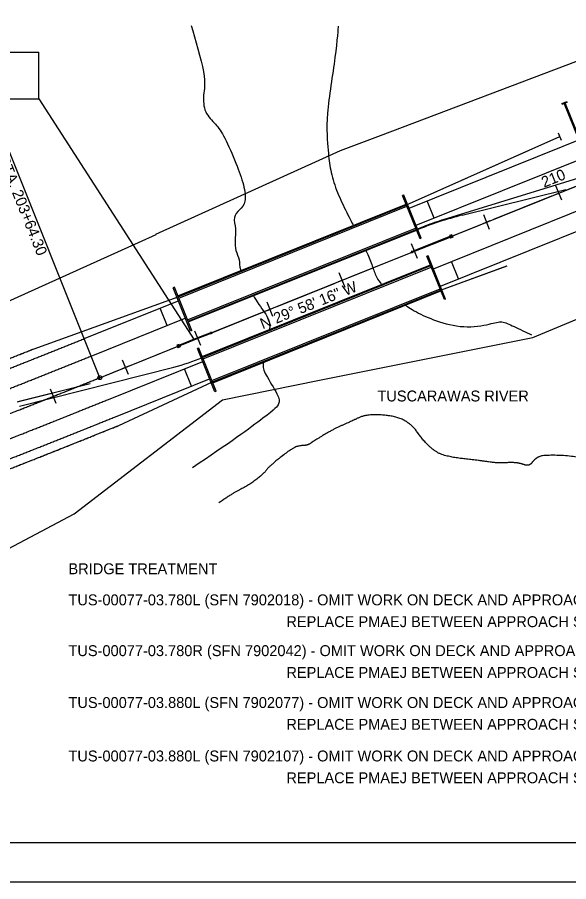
# Model space of a CAD drawing. Extents: x 0 to 3400, y 0 to 2200.
# Drawn here: x 2284 to 2993, y 0 to 1110 of the extents above; entities that cross this region are included whole.
import ezdxf

# ---------------------------------------------------------------- set-up
doc = ezdxf.new("R2010")
doc.units = 0
for name, color, linetype in [('Default', 7, 'Continuous'), ('DR_X_Culvert', 7, 'Continuous'), ('GE_P_CL_100', 7, 'Continuous'), ('HY_X_Text', 7, 'Continuous'), ('HY_X_Water_Edge', 7, 'Continuous'), ('PV_P_EOP', 7, 'Continuous'), ('RD_P_GR_Rt_Replaced', 7, 'Continuous'), ('RD_X_GR_Lt', 7, 'Continuous'), ('RD_X_GR_Rt', 7, 'Continuous'), ('RW_X_Esmt_LA', 7, 'Continuous'), ('SC_Scratch10', 7, 'Continuous'), ('SH_Border', 7, 'Continuous'), ('SH_Cut_Line', 7, 'Continuous'), ('SH_Data', 7, 'Continuous')]:
    doc.layers.add(name, color=color, linetype=linetype)

msp = doc.modelspace()

# ---------------------------------------------------------------- linework, layer by layer
at = {"layer": 'Default'}
for p, q in [((2784.4, 868.8), (2958.6, 946.4)), ((2784.4, 868.8), (2958.6, 946.4)), ((2516.4, 697.6), (3073.1, 921.3)), ((2856.1, 855.7), (2989.4, 888.6)), ((2856.1, 855.7), (2989.4, 888.6)), ((2984.1, 874.7), (2976.6, 893.3)), ((2781.1, 881.5), (2779.5, 880.9)), ((2801.9, 825.2), (2779.5, 880.9)), ((2803.5, 825.9), (2781.1, 881.5)), ((2980.3, 884), (2980.3, 884)), ((2983.1, 885.1), (2983.1, 885.1)), ((2490.8, 751.9), (2784, 869.7)), ((2491.1, 751), (2784.4, 868.8)), ((2491.9, 749.2), (2785.1, 867)), ((2820, 851.9), (2811, 874.2)), ((2891.3, 837.4), (2883.8, 856)), ((2503.1, 721.3), (2796.3, 839.1)), ((2503.8, 719.5), (2797, 837.3)), ((2504.2, 718.5), (2797.4, 836.3)), ((2803.5, 825.9), (2801.9, 825.2)), ((2798.5, 800.1), (2791, 818.7)), ((2812.4, 803.6), (2810.8, 802.9)), ((2833.2, 747.3), (2810.8, 802.9)), ((2834.8, 747.9), (2812.4, 803.6)), ((2522.1, 674), (2815.3, 791.8)), ((2522.5, 673.1), (2815.7, 790.9)), ((2523.2, 671.2), (2816.4, 789)), ((2828.3, 759.3), (2913.9, 790.6)), ((2828.3, 759.3), (2913.6, 790.5)), ((2851.3, 773.9), (2842.4, 796.2)), ((2705.7, 762.9), (2698.2, 781.4)), ((2486.3, 763.1), (2484.7, 762.4)), ((2507, 706.8), (2484.7, 762.4)), ((2508.7, 707.4), (2486.3, 763.1)), ((2534.4, 643.4), (2827.6, 761.2)), ((2535.1, 641.5), (2828.3, 759.3)), ((2535.5, 640.6), (2828.7, 758.4)), ((2306.1, 684.2), (2491.1, 751)), ((2306.1, 684.2), (2491.1, 751)), ((2612.9, 725.6), (2605.4, 744.1)), ((2834.8, 747.9), (2833.2, 747.3)), ((2477.1, 714.1), (2468.2, 736.4)), ((2508.7, 707.4), (2507, 706.8)), ((2520.1, 688.3), (2512.6, 706.8)), ((2390.5, 647), (2516.4, 697.6)), ((2517.6, 685.1), (2516, 684.5)), ((2538.4, 628.8), (2516, 684.5)), ((2540, 629.5), (2517.6, 685.1)), ((2427.3, 651), (2419.8, 669.6)), ((2287.1, 610.4), (2485.6, 660.4)), ((2508.4, 636.2), (2499.5, 658.5)), ((2285.3, 616.4), (2378, 639.4)), ((2378, 639.4), (2378, 639.4)), ((2415.1, 585.7), (2535.1, 641.5)), ((2415.1, 585.7), (2535.1, 641.5)), ((2334.5, 613.8), (2327.1, 632.3)), ((2540, 629.5), (2538.4, 628.8)), ((2287.1, 610.4), (2287.1, 610.4))]:
    msp.add_line(p, q, dxfattribs=at)
for points in [[(2989.6, 887.7), (3063.8, 917.5)], [(2896.8, 850.4), (2971.1, 880.3)], [(2975.7, 882.1), (2985, 885.8)], [(2882.9, 844.8), (2892.2, 848.6)], [(2804, 813.1), (2878.3, 843)], [(2711.2, 775.9), (2785.5, 805.7)], [(2618.4, 738.6), (2692.7, 768.4)], [(2697.3, 770.3), (2706.6, 774)], [(2604.5, 733), (2613.8, 736.7)], [(2525.7, 701.3), (2599.9, 731.1)], [(2432.9, 664), (2507.1, 693.8)], [(2340.1, 626.8), (2341.9, 627.5), (2344.8, 628.6), (2347.7, 629.8), (2350.5, 630.9), (2353.4, 632.1), (2356.2, 633.2), (2359.1, 634.4), (2361.9, 635.5), (2364.8, 636.7), (2367.6, 637.8), (2370.5, 639), (2373.4, 640.1), (2376.2, 641.2), (2379.1, 642.4), (2381.9, 643.5), (2384.8, 644.7), (2387.6, 645.8), (2390.5, 647), (2390.5, 647), (2414.3, 656.6)], [(2418.9, 658.4), (2423.6, 660.3)], [(2423.6, 660.3), (2428.2, 662.1)], [(2326.1, 621.2), (2327.6, 621.8), (2330.5, 622.9), (2330.8, 623)], [(2330.8, 623), (2333.4, 624.1), (2335.4, 624.9)], [(2281.9, 603.7), (2284.7, 604.8), (2287.6, 605.9), (2290.5, 607), (2293.3, 608.2), (2296.2, 609.3), (2299.1, 610.4), (2301.9, 611.6), (2304.8, 612.7), (2307.6, 613.8), (2310.5, 615), (2313.4, 616.1), (2316.2, 617.2), (2319.1, 618.4), (2321.5, 619.3)]]:
    msp.add_lwpolyline(points, dxfattribs=at)
for centre, radius, start, end in [((2956.4, 449.7), 418.1, 103.87, 112.4671), ((2956.4, 449.7), 418.1, 103.87, 112.4671), ((2401.1, 966.1), 317.2, 285.4481, 292.5011)]:
    msp.add_arc(centre, radius, start, end, dxfattribs=at)
for points in [[(2219.8, 650.3), (2223.7, 651.8), (2229.3, 654), (2235, 656.2), (2240.7, 658.4), (2246.4, 660.6), (2252.1, 662.9), (2257.7, 665.1), (2263.4, 667.3), (2269.1, 669.6), (2274.8, 671.8), (2280.5, 674.1), (2286.1, 676.3), (2291.8, 678.6), (2297.5, 680.8), (2303.2, 683.1), (2306.1, 684.2)], [(2219.8, 650.3), (2223.7, 651.8), (2229.3, 654), (2235, 656.2), (2240.7, 658.4), (2246.4, 660.6), (2252.1, 662.9), (2257.7, 665.1), (2263.4, 667.3), (2269.1, 669.6), (2274.8, 671.8), (2280.5, 674.1), (2286.1, 676.3), (2291.8, 678.6), (2297.5, 680.8), (2303.2, 683.1), (2306.1, 684.2)], [(2140.2, 550.2), (2143.7, 551.5), (2149.5, 553.5), (2155.3, 555.6), (2161.1, 557.7), (2166.9, 559.8), (2172.6, 562), (2178.4, 564.1), (2184.2, 566.2), (2190, 568.4), (2195.7, 570.5), (2201.5, 572.7), (2207.2, 574.9), (2213, 577), (2218.8, 579.2), (2224.5, 581.4), (2230.3, 583.6), (2236, 585.8), (2241.7, 588), (2247.5, 590.2), (2253.2, 592.5), (2259, 594.7), (2264.7, 596.9), (2270.4, 599.2), (2276.2, 601.4), (2281.9, 603.7), (2287.6, 605.9), (2293.3, 608.2), (2299.1, 610.4), (2304.8, 612.7), (2310.5, 615), (2316.2, 617.2), (2321.9, 619.5), (2327.6, 621.8), (2333.4, 624.1), (2339.1, 626.4), (2344.8, 628.6), (2350.5, 630.9), (2356.2, 633.2), (2361.9, 635.5), (2367.6, 637.8), (2373.4, 640.1), (2379.1, 642.4), (2384.8, 644.7), (2390.5, 647)], [(2173.9, 492.2), (2177.8, 493.6), (2183.7, 495.7), (2189.5, 497.9), (2195.4, 500), (2201.3, 502.2), (2207.2, 504.3), (2213, 506.5), (2218.9, 508.7), (2224.7, 510.9), (2230.6, 513.1), (2236.4, 515.3), (2242.2, 517.5), (2248.1, 519.7), (2253.9, 522), (2259.7, 524.2), (2265.5, 526.4), (2271.3, 528.7), (2277.1, 530.9), (2282.9, 533.2), (2288.7, 535.4), (2294.5, 537.7), (2300.3, 540), (2306, 542.2), (2311.8, 544.5), (2317.6, 546.8), (2323.3, 549.1), (2329.1, 551.3), (2334.9, 553.6), (2340.6, 555.9), (2346.4, 558.2), (2352.1, 560.5), (2357.8, 562.8), (2363.6, 565.1), (2369.3, 567.4), (2375.1, 569.7), (2380.8, 572), (2386.5, 574.3), (2392.2, 576.6), (2397.9, 578.9), (2403.7, 581.2), (2409.4, 583.4), (2415.1, 585.7)], [(2173.9, 492.2), (2177.8, 493.6), (2183.7, 495.7), (2189.5, 497.9), (2195.4, 500), (2201.3, 502.2), (2207.2, 504.3), (2213, 506.5), (2218.9, 508.7), (2224.7, 510.9), (2230.6, 513.1), (2236.4, 515.3), (2242.2, 517.5), (2248.1, 519.7), (2253.9, 522), (2259.7, 524.2), (2265.5, 526.4), (2271.3, 528.7), (2277.1, 530.9), (2282.9, 533.2), (2288.7, 535.4), (2294.5, 537.7), (2300.3, 540), (2306, 542.2), (2311.8, 544.5), (2317.6, 546.8), (2323.3, 549.1), (2329.1, 551.3), (2334.9, 553.6), (2340.6, 555.9), (2346.4, 558.2), (2352.1, 560.5), (2357.8, 562.8), (2363.6, 565.1), (2369.3, 567.4), (2375.1, 569.7), (2380.8, 572), (2386.5, 574.3), (2392.2, 576.6), (2397.9, 578.9), (2403.7, 581.2), (2409.4, 583.4), (2415.1, 585.7)]]:
    msp.add_spline(points, degree=3, dxfattribs=at)
at = {"layer": 'DR_X_Culvert'}
for p, q in [((2984.2, 999.1), (2990.7, 1001.7)), ((2984.2, 999.1), (2984.6, 998.1)), ((2984.6, 998.1), (2991.1, 1000.7)), ((3025.2, 904.7), (2986.9, 1000.1)), ((3026.4, 905.2), (2988, 1000.6)), ((2990.7, 1001.7), (2991.1, 1000.7)), ((2841, 828.5), (2790.9, 808.4)), ((2841.3, 827.6), (2791.2, 807.5)), ((2843, 830.6), (2839.9, 829.4)), ((2839.9, 829.4), (2841.1, 826.3)), ((2842.6, 829.7), (2840.8, 829)), ((2840.8, 829), (2841.5, 827.1)), ((2841.1, 828.1), (2841.1, 828.1)), ((2844.2, 827.5), (2841.1, 826.3)), ((2843.4, 827.9), (2841.5, 827.1)), ((2842.6, 829.7), (2843.4, 827.9)), ((2843, 830.6), (2844.2, 827.5)), ((2791.6, 809.1), (2790.7, 808.8)), ((2790.7, 808.8), (2791.4, 807.1)), ((2791, 807.9), (2791, 807.9)), ((2792.3, 807.4), (2791.4, 807.1)), ((2791.6, 809.1), (2792.3, 807.4)), ((2533.8, 705.1), (2516.2, 698)), ((2534.2, 704.2), (2516.6, 697.1)), ((2533.7, 705.5), (2532.7, 705.1)), ((2532.7, 705.1), (2533.4, 703.4)), ((2534.4, 703.8), (2533.4, 703.4)), ((2533.7, 705.5), (2534.4, 703.8)), ((2534, 704.7), (2534, 704.7)), ((2492.6, 689.8), (2489.5, 688.6)), ((2489.5, 688.6), (2490.7, 685.5)), ((2492.2, 688.9), (2490.3, 688.2)), ((2490.3, 688.2), (2491.1, 686.3)), ((2492.2, 688.9), (2492.9, 687.1)), ((2492.6, 689.8), (2493.8, 686.7)), ((2516.2, 698), (2493, 688.7)), ((2493.2, 688.2), (2493.2, 688.2)), ((2516.6, 697.1), (2493.4, 687.8)), ((2516.4, 697.6), (2516.4, 697.6)), ((2493.8, 686.7), (2490.7, 685.5)), ((2492.9, 687.1), (2491.1, 686.3))]:
    msp.add_line(p, q, dxfattribs=at)
for points in [[(2511.7, 695.7), (2516.4, 697.6)], [(2516.4, 697.6), (2516.4, 697.6)]]:
    msp.add_lwpolyline(points, dxfattribs=at)
at = {"layer": 'HY_X_Water_Edge'}
for points, degree in [([(2508, 1098.9), (2513.2, 1081.7), (2528.1, 1030.3), (2522.8, 1010.5), (2524.2, 986.7), (2539.8, 972.4), (2550.3, 958.3), (2566.3, 920.8), (2576.1, 893.9), (2579, 871.1), (2569.8, 862.6), (2561.1, 853.6), (2566, 838), (2563.9, 822.5), (2564.4, 810.4), (2570.9, 797.8), (2569.6, 791), (2571.5, 784.7)], 3), ([(2696.8, 1098.3), (2696.7, 1096.9), (2694.5, 1063.9), (2680, 979.8), (2684.1, 935.4), (2686.3, 914.3), (2694, 887.7), (2706, 862.4), (2714.7, 845.3), (2716, 842.8)], 3), ([(2732.4, 810.2), (2732.9, 809.1), (2739.2, 795.6), (2743.5, 781.1), (2747.5, 772.8), (2752.2, 767.3)], 3), ([(2587.8, 752.1), (2588.6, 750.9), (2595.3, 739.8), (2602.5, 731.1), (2607.9, 720.8), (2609.1, 715), (2608.5, 709.3)], 3), ([(2782.7, 740.4), (2783.6, 739.7), (2796.2, 731.1), (2821.1, 719.9), (2858.1, 709.8), (2894.6, 716), (2906.9, 720.6), (2920.6, 713.4), (2938.4, 705.3), (2945.1, 702.1)], 3), ([(2600.5, 666.9), (2599.6, 659.8), (2601.5, 653.8), (2621, 622.8), (2621.9, 613.5), (2612.8, 603.7), (2555.7, 562.1), (2509.7, 531.5)], 3), ([(3073.2, 546.9), (3045, 548.5), (3038.4, 536.6), (3033.6, 529.9), (3016.3, 537.1), (3006, 546), (2961, 548.1), (2949.8, 543.4), (2942.1, 532.9), (2929.7, 537.6), (2916.8, 538.2), (2902.2, 537.1), (2870.7, 541.7), (2847, 544), (2823.9, 549.5), (2805.1, 567.2), (2793.2, 584.8), (2776.5, 595.7), (2754, 599.6), (2729.9, 599), (2714, 591.1), (2690.6, 580.9), (2666.4, 566.4), (2657.9, 560.2), (2647.7, 559.9), (2638.2, 556.9), (2609.5, 534.6), (2600.4, 523.1), (2582.7, 509.5), (2561.3, 498.8), (2543.4, 486.2)], 2)]:
    msp.add_open_spline(points, degree=degree, dxfattribs=at)
at = {"layer": 'PV_P_EOP'}
for p, q in [((2787.8, 864.8), (3053, 971.4)), ((2796.8, 842.6), (3061.9, 949.1)), ((2819.2, 786.9), (3084.3, 893.4)), ((2828.1, 764.6), (3093.3, 871.2)), ((2370.4, 697.1), (2491.4, 745.7)), ((2379.3, 674.8), (2500.3, 723.4)), ((2401.7, 619.1), (2522.7, 667.8)), ((2410.6, 596.9), (2531.6, 645.5))]:
    msp.add_line(p, q, dxfattribs=at)
for points in [[(2161.9, 615.6), (2165.4, 616.9), (2171.1, 619), (2176.8, 621.1), (2182.5, 623.2), (2188.2, 625.4), (2193.9, 627.5), (2199.6, 629.7), (2205.2, 631.9), (2210.9, 634), (2216.6, 636.2), (2222.3, 638.4), (2228, 640.6), (2233.7, 642.8), (2239.4, 645), (2245.1, 647.2), (2250.7, 649.5), (2256.4, 651.7), (2262.1, 653.9), (2267.8, 656.2), (2273.5, 658.4), (2279.2, 660.6), (2284.9, 662.9), (2290.6, 665.2), (2296.3, 667.4), (2302, 669.7), (2307.6, 672), (2313.3, 674.2), (2319, 676.5), (2324.7, 678.8), (2330.4, 681.1), (2336.1, 683.3), (2341.8, 685.6), (2347.5, 687.9), (2353.2, 690.2), (2358.9, 692.5), (2364.6, 694.8), (2370.4, 697.1)], [(2158, 588.5), (2162.3, 590.1), (2168, 592.2), (2173.8, 594.4), (2179.5, 596.5), (2185.2, 598.6), (2190.9, 600.8), (2196.7, 602.9), (2202.4, 605.1), (2208.1, 607.3), (2213.8, 609.4), (2219.5, 611.6), (2225.2, 613.8), (2230.9, 616), (2236.7, 618.2), (2242.4, 620.4), (2248.1, 622.6), (2253.8, 624.9), (2259.5, 627.1), (2265.2, 629.3), (2270.9, 631.6), (2276.6, 633.8), (2282.3, 636.1), (2288, 638.3), (2293.7, 640.6), (2299.4, 642.9), (2305.1, 645.1), (2310.8, 647.4), (2316.5, 649.7), (2322.2, 651.9), (2327.9, 654.2), (2333.6, 656.5), (2339.4, 658.8), (2345.1, 661.1), (2350.8, 663.4), (2356.5, 665.6), (2362.2, 667.9), (2367.9, 670.2), (2373.6, 672.5), (2379.3, 674.8)], [(2153.9, 523.3), (2159.7, 525.3), (2165.5, 527.4), (2171.3, 529.5), (2177.2, 531.7), (2183, 533.8), (2188.8, 535.9), (2194.6, 538.1), (2200.4, 540.3), (2206.2, 542.4), (2212, 544.6), (2217.8, 546.8), (2223.6, 549), (2229.4, 551.2), (2235.2, 553.4), (2241, 555.6), (2246.8, 557.8), (2252.5, 560), (2258.3, 562.3), (2264.1, 564.5), (2269.8, 566.7), (2275.6, 569), (2281.4, 571.2), (2287.1, 573.5), (2292.9, 575.7), (2298.6, 578), (2304.4, 580.3), (2310.1, 582.5), (2315.8, 584.8), (2321.6, 587.1), (2327.3, 589.4), (2333, 591.6), (2338.8, 593.9), (2344.5, 596.2), (2350.2, 598.5), (2355.9, 600.8), (2361.7, 603.1), (2367.4, 605.4), (2373.1, 607.7), (2378.8, 610), (2384.5, 612.3), (2390.2, 614.6), (2396, 616.9), (2401.7, 619.1)], [(2150.4, 496.5), (2156, 498.5), (2161.9, 500.6), (2167.8, 502.7), (2173.7, 504.9), (2179.6, 507), (2185.4, 509.1), (2191.3, 511.3), (2197.1, 513.4), (2203, 515.6), (2208.8, 517.8), (2214.7, 520), (2220.5, 522.1), (2226.3, 524.3), (2232.1, 526.5), (2238, 528.7), (2243.8, 531), (2249.6, 533.2), (2255.4, 535.4), (2261.2, 537.6), (2267, 539.9), (2272.8, 542.1), (2278.5, 544.4), (2284.3, 546.6), (2290.1, 548.9), (2295.9, 551.1), (2301.6, 553.4), (2307.4, 555.7), (2313.2, 557.9), (2318.9, 560.2), (2324.7, 562.5), (2330.4, 564.8), (2336.2, 567.1), (2341.9, 569.4), (2347.7, 571.6), (2353.4, 573.9), (2359.1, 576.2), (2364.9, 578.5), (2370.6, 580.8), (2376.3, 583.1), (2382, 585.4), (2387.8, 587.7), (2393.5, 590), (2399.2, 592.3), (2404.9, 594.6), (2410.6, 596.9)]]:
    msp.add_spline(points, degree=3, dxfattribs=at)
at = {"layer": 'RD_P_GR_Rt_Replaced'}
msp.add_line((2979.6, 961.2), (2983.3, 951.9), dxfattribs=at)
at = {"layer": 'RD_X_GR_Lt'}
msp.add_line((2485.6, 660.4), (2485.5, 660.4), dxfattribs=at)
for points in [[(2784.4, 868.8), (2981.4, 956.5)], [(2283.3, 675.2), (2286.1, 676.3), (2289, 677.4), (2291.8, 678.6), (2294.7, 679.7), (2297.5, 680.8), (2300.4, 682), (2303.2, 683.1), (2304.6, 683.7), (2306.1, 684.2), (2491.1, 751)], [(2287.1, 610.4), (2485.6, 660.4)]]:
    msp.add_lwpolyline(points, dxfattribs=at)
msp.add_arc((2401.1, 966.1), 317.2, 285.4477, 292.5011, dxfattribs=at)
at = {"layer": 'RD_X_GR_Rt'}
for p, q in [((2832.3, 850), (3011.4, 905.4)), ((2797, 837.3), (2808.7, 841.8)), ((2284.4, 616.2), (2378, 639.4))]:
    msp.add_line(p, q, dxfattribs=at)
for points in [[(2828.3, 759.3), (2913.9, 790.6)], [(2282.9, 533.2), (2285.8, 534.3), (2288.7, 535.4), (2291.6, 536.6), (2294.5, 537.7), (2297.4, 538.8), (2300.3, 540), (2303.1, 541.1), (2306, 542.2), (2308.9, 543.4), (2311.8, 544.5), (2314.7, 545.6), (2317.6, 546.8), (2320.5, 547.9), (2323.3, 549.1), (2326.2, 550.2), (2329.1, 551.3), (2332, 552.5), (2334.9, 553.6), (2337.7, 554.8), (2340.6, 555.9), (2343.5, 557.1), (2346.4, 558.2), (2349.2, 559.3), (2352.1, 560.5), (2355, 561.6), (2357.8, 562.8), (2360.7, 563.9), (2363.6, 565.1), (2366.5, 566.2), (2369.3, 567.4), (2372.2, 568.5), (2375.1, 569.7), (2377.9, 570.8), (2380.8, 572), (2383.6, 573.1), (2386.5, 574.3), (2389.4, 575.4), (2392.2, 576.6), (2395.1, 577.7), (2397.9, 578.9), (2400.8, 580), (2403.7, 581.2), (2406.5, 582.3), (2409.4, 583.4), (2412.2, 584.6), (2415.1, 585.7), (2535.1, 641.5)]]:
    msp.add_lwpolyline(points, dxfattribs=at)
msp.add_arc((2948.6, 477.4), 390.3, 107.3308, 111.0011, dxfattribs=at)
at = {"layer": 'RW_X_Esmt_LA'}
for p, q in [((2751.3, 957.9), (3017.8, 1058.9)), ((2699.7, 938.8), (2751.3, 957.9)), ((2462.6, 831.3), (2699.7, 938.8)), ((2440, 820.5), (2462.8, 830.9)), ((2167.6, 697.8), (2440, 820.5)), ((2947, 698.7), (3131.6, 775.7)), ((2672.6, 644), (2947, 698.7)), ((2548.1, 618.7), (2672.6, 644)), ((2357.7, 472.3), (2548.1, 618.7)), ((2154.7, 364.6), (2357.7, 472.3))]:
    msp.add_line(p, q, dxfattribs=at)
at = {"layer": 'SC_Scratch10'}
for p, q in [((2980.3, 884), (2980.3, 884)), ((2887.5, 846.7), (2887.5, 846.7)), ((2794.8, 809.4), (2794.8, 809.4)), ((2702, 772.1), (2702, 772.1)), ((2609.2, 734.9), (2609.2, 734.9)), ((2516.4, 697.6), (2516.4, 697.6)), ((2423.6, 660.3), (2423.6, 660.3)), ((2330.8, 623), (2330.8, 623))]:
    msp.add_line(p, q, dxfattribs=at)
at = {"layer": 'SH_Border'}
msp.add_lwpolyline([(150, 2150), (3350, 2150), (3350, 50), (150, 50)], close=True, dxfattribs=at)
at = {"layer": 'SH_Cut_Line'}
msp.add_lwpolyline([(0, 0), (3400, 0), (3400, 2200), (0, 2200)], close=True, dxfattribs=at)
at = {"layer": 'SH_Data'}
for p, q in [((2057.7, 1064.7), (2312, 1064.8)), ((2312, 1004.8), (2312, 1064.8)), ((2057.7, 1004.7), (2312, 1004.8)), ((2312, 1004.8), (2511.5, 695.6)), ((2390.5, 647), (2259.3, 973.4))]:
    msp.add_line(p, q, dxfattribs=at)
for points in [[(2790.1, 807.6), (2799.4, 811.3)], [(2516.4, 697.6), (2521, 699.4)]]:
    msp.add_lwpolyline(points, dxfattribs=at)
msp.add_circle((2390.5, 647), 2.5, dxfattribs=at)

# ---------------------------------------------------------------- texts
at = {"layer": 'Default'}
for s, p in [('BRIDGE TREATMENT', (2350.2, 394.7)), ('TUS-00077-03.780L (SFN 7902018) - OMIT WORK ON DECK AND APPROACH SLABS. ', (2350.2, 354.8)), ('REPLACE PMAEJ BETWEEN APPROACH SLABS AND PAVEMENT.', (2630.2, 326.8)), ('TUS-00077-03.780R (SFN 7902042) - OMIT WORK ON DECK AND APPROACH SLABS. ', (2350.2, 289.6)), ('REPLACE PMAEJ BETWEEN APPROACH SLABS AND PAVEMENT.', (2630.2, 261.6)), ('TUS-00077-03.880L (SFN 7902077) - OMIT WORK ON DECK AND APPROACH SLABS. ', (2350.2, 223)), ('REPLACE PMAEJ BETWEEN APPROACH SLABS AND PAVEMENT.', (2630.2, 195)), ('TUS-00077-03.880L (SFN 7902107) - OMIT WORK ON DECK AND APPROACH SLABS. ', (2350.2, 154.4)), ('REPLACE PMAEJ BETWEEN APPROACH SLABS AND PAVEMENT.', (2630.2, 126.4))]:
    msp.add_text(s, height=14, dxfattribs=at).set_placement(p)
at = {"layer": 'GE_P_CL_100'}
for s, rotation, p in [('S.T. STA. 203+64.30', 291.8916, (2245.1, 965)), ('210', 21.8912, (2961.3, 890.8)), ('N 29%%d 58\' 16" W', 21.8894, (2599.8, 709.1))]:
    msp.add_text(s, height=14, rotation=rotation, dxfattribs=at).set_placement(p)
at = {"layer": 'HY_X_Text'}
msp.add_text('TUSCARAWAS RIVER', height=14, dxfattribs=at).set_placement((2747.2, 616.5))

doc.saveas('drawing.dxf')
